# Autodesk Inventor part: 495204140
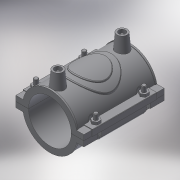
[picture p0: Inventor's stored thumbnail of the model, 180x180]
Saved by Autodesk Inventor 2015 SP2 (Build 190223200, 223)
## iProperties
Created: 2017-07
Part Number: 495204140
Material: Generic
Description: PLASSON REPAIR SADDLE 140
Document SubType Name: Modeling
Designer: KIM
Density: 1 g/cm^3
Appearance: Default
Author: KIM
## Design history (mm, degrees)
derived "495204.ipt"
feature "Solid1::495204.ipt"
tag "TaggingFeature1"
body "Solid1"
other parameters: "d1" = 165.2, "d3" = 35, "d4" = 118, "d5" = 0, "d6" = 0.1, "d8" = 0, "d19" = 6, "d20" = 6, "d21" = 70.8, "d23" = 0, "d24" = 35.4, "d26" = 0, "d27" = 3, "d28" = 3, "d29" = 3, "d30" = 46.66667, "d31" = 6, "d32" = 0, "d33" = 0, "d34" = 0.6, "d40" = 85.904, "d41" = 64.9, "d43" = 0, "d45" = 0, "d47" = 89.208, "d48" = 47.2, "d50" = 0, "d70" = 15, "d72" = 0, "d73" = 6, "d75" = 5, "d76" = 0, "d77" = 7, "d78" = 99, "d79" = 15, "d80" = 47.2, "d82" = 5 deg, "d84" = 4, "d85" = 14, "d86" = 0, "d87" = 3, "d88" = 0, "d89" = 1, "d90" = 1, "d91" = 94.4, "d92" = 0, "d93" = 0.5, "d94" = 73.68421, "d96" = 168.504, "d97" = 2.36, "d98" = 0, "d99" = 47.2, "d100" = 0, "d102" = 3.54, "H_" = 29, "L_" = 118, "d_t" = 6
